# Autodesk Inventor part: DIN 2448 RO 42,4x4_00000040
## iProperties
Created: 2006-02
Part Number: DIN 2448 RO 42,4x4_00000040
Material: Default
Document SubType Name: Modeling
Designer: FranzK
Stock Number: DIN 2448 RO 42,4x4
Mass: 75.7986 g
Surface Area: 388.644 cm^2
Volume: 75.7986 cm^3
Density: 1 g/cm^3
G_L: 157.080 mm
G_W: 42.400 mm
G_H: 42.400 mm
AFG_Item: 42.4 x 4
CSToolsMass: 0.1
CSToolsVolume: 75799.0
CSToolsArea: 389.0
Author: FranzK
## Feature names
1. AFG_Detailed_DIN 2448 RO 42,4x4_00000040
2. AFG_Simplified_DIN 2448 RO 42,4x4_00000040
